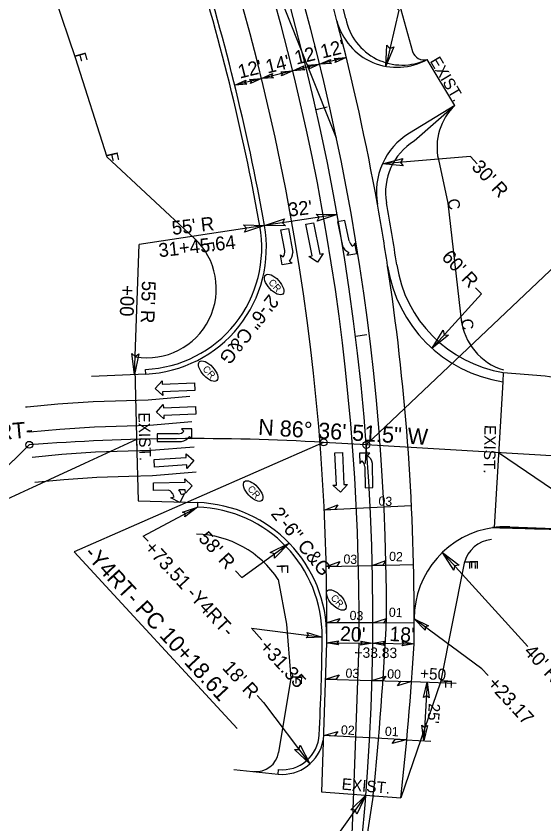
# Model space of a CAD drawing. Extents: x 1702862 to 1704514, y 793768 to 796215.
# Drawn here: x 1703833.9 to 1704063.5, y 794035 to 794386.1 of the extents above; entities that cross this region are included whole.
import ezdxf

# ---------------------------------------------------------------- set-up
doc = ezdxf.new("R2010")
doc.units = 0
for name, color, linetype in [('Exist Horizontal Alignment', 7, 'Continuous'), ('Exist Horizontal Alignment Station Label', 7, 'Continuous'), ('Exist Horizontal Alignment Tick Large', 7, 'Continuous'), ('Old_Level_3', 7, 'Continuous'), ('Prop Conc 2ft 6in Curb and Gutter', 7, 'Continuous'), ('Prop Dimension', 7, 'Continuous'), ('Prop Dimension Text', 7, 'Continuous'), ('Prop DSN Text', 7, 'Continuous'), ('Prop EOT', 7, 'Continuous'), ('Prop Horizontal Alignment', 7, 'Continuous'), ('Prop Horizontal Alignment Direction Label', 7, 'Continuous'), ('Prop Horizontal Alignment Station Label', 7, 'Continuous'), ('Prop Horizontal Alignment Tick Small', 7, 'Continuous'), ('Prop Lane Arrow CELL', 7, 'Continuous'), ('Prop Lane Lines', 7, 'Continuous'), ('Prop Leader Line Medium', 7, 'Continuous'), ('Prop Paved Shoulder', 7, 'Continuous'), ('Prop SS Cut Line', 7, 'Continuous'), ('Prop SS Fill Line', 7, 'Continuous'), ('Prop SS Misc', 7, 'Continuous'), ('Prop SS Transition Line', 7, 'Continuous'), ('Prop Superelevation  Arrow CELL', 7, 'Continuous'), ('Prop Superelevation Label', 7, 'Continuous'), ('Prop Terminator CELL', 7, 'Continuous'), ('Prop WCR CELL', 7, 'Continuous')]:
    doc.layers.add(name, color=color, linetype=linetype)

msp = doc.modelspace()

# ---------------------------------------------------------------- linework, layer by layer
at = {"layer": 'Exist Horizontal Alignment'}
msp.add_line((1703986.29, 794199.72), (1703967.71, 794200.82), dxfattribs=at)
msp.add_arc((1703911.32, 793247.48), 955, 86.61431, 94.30234, dxfattribs=at)
at = {"layer": 'Exist Horizontal Alignment Station Label'}
for p, q in [((1703809.32, 794169.99), (1703839.67, 794199.79)), ((1703967.71, 794200.82), (1703859.14, 794153.32)), ((1703859.14, 794153.32), (1703930.08, 794076.46))]:
    msp.add_line(p, q, dxfattribs=at)
for centre in [(1703967.71, 794200.82), (1703839.67, 794199.79), (1703986.29, 794199.72)]:
    msp.add_circle(centre, 1.5, dxfattribs=at)
at = {"layer": 'Exist Horizontal Alignment Tick Large'}
msp.add_line((1703986.29, 794199.72), (1703985.82, 794191.73), dxfattribs=at)
at = {"layer": 'Old_Level_3'}
for points in [[(1704045.87, 794231.21), (1704074.98, 794228.45), (1704097.71, 794224.72)], [(1704093.48, 794162.67), (1704041.88, 794163.83), (1704068.07, 794163.09)]]:
    msp.add_spline(points, degree=3, dxfattribs=at)
at = {"layer": 'Prop Conc 2ft 6in Curb and Gutter'}
for p, q in [((1703890.33, 794230.53), (1703890.23, 794232.53)), ((1703912.86, 794174.66), (1703912.8, 794172.67)), ((1703947.93, 794056.66), (1703948.13, 794058.65))]:
    msp.add_line(p, q, dxfattribs=at)
for centre, radius, start, end in [((1702989.11, 794124.65), 966, 10.14602, 17.69698), ((1703887.83, 794285.48), 53, 272.5979, 10.146), ((1703911.08, 794116.69), 56, 359.5057, 88.2385), ((1702989.11, 794124.65), 978, 357.01557, 359.50571), ((1703949.8, 794074.56), 16, 264.0066, 357.0156)]:
    msp.add_arc(centre, radius, start, end, dxfattribs=at)
at = {"layer": 'Prop Dimension'}
for p, q in [((1703977.58, 794368.05), (1703960.1, 794363.75)), ((1703960.1, 794363.75), (1703929.03, 794356.1)), ((1703973.64, 794299.88), (1703941.98, 794295.11)), ((1703969.03, 794113.76), (1703989.05, 794113.54)), ((1703989.05, 794113.54), (1704007.05, 794113.34))]:
    msp.add_line(p, q, dxfattribs=at)
msp.add_lwpolyline([(1704033.81, 794268.08), (1704036.35, 794265.34), (1704014.88, 794241.77)], dxfattribs=at)
at = {"layer": 'Prop Dimension Text'}
for p in [(1703941.97, 794295.17), (1703885.5, 794230.32)]:
    msp.add_line(p, (1703887.5, 794286.9), dxfattribs=at)
for points in [[(1703997.7, 794391.74), (1704000.49, 794388.71), (1703994.76, 794364.3)], [(1704034.48, 794321.92), (1704031.62, 794325.02), (1703993.3, 794321.91)], [(1703891.33, 794157.83), (1703889.2, 794160.09), (1703912.79, 794172.69)], [(1703929.42, 794144.98), (1703932.09, 794142.08), (1703952.72, 794157.07)], [(1704056.52, 794112.19), (1704053.8, 794115.14), (1704019.4, 794153.02)], [(1704039.27, 794099.52), (1704036.54, 794102.47), (1704007.11, 794124.19)], [(1703940.9, 794115.03), (1703936.28, 794120.03), (1703967.07, 794116.21)], [(1703938.74, 794090.78), (1703941.53, 794087.76), (1703961.72, 794061.07)]]:
    msp.add_lwpolyline(points, dxfattribs=at)
at = {"layer": 'Prop EOT'}
for p, q in [((1704024.85, 794347.32), (1704012.71, 794367.19)), ((1704024.85, 794347.32), (1704005.02, 794335.21)), ((1703890.33, 794230.53), (1703866.68, 794229.46)), ((1703885.56, 794232.69), (1703886.49, 794197.16)), ((1704045.63, 794227.2), (1704041.88, 794163.83)), ((1703886.36, 794202.16), (1703887.05, 794175.46)), ((1703887.05, 794175.46), (1703912.86, 794174.66)), ((1703969.03, 794113.76), (1703966.73, 794048.94)), ((1703928.6, 794058.69), (1703947.93, 794056.66)), ((1703966.73, 794048.94), (1704001.25, 794046.28))]:
    msp.add_line(p, q, dxfattribs=at)
for centre, radius, start, end in [((1702989.11, 794124.65), 1018, 14.75888, 42.70907), ((1702989.11, 794124.65), 968, 10.14602, 17.69698), ((1703999.63, 794390.86), 27, 194.7589, 299.2661), ((1704020.66, 794309.61), 30, 121.4124, 190.1653), ((1702989.11, 794124.65), 1018, 8.63399, 10.1653), ((1703887.83, 794285.48), 55, 272.5979, 10.146), ((1704054.89, 794286.48), 60, 188.634, 261.1171), ((1703911.08, 794116.69), 58, 359.5057, 88.2385), ((1704047.11, 794124.17), 40, 97.5132, 179.9743), ((1702989.11, 794124.65), 1018, 359.36375, 359.9743), ((1702989.11, 794124.65), 980, 359.36375, 359.50571), ((1702759.73, 794187.37), 1249.51, 353.51674, 356.60361), ((1703949.8, 794074.56), 18, 264.0066, 349.9892)]:
    msp.add_arc(centre, radius, start, end, dxfattribs=at)
at = {"layer": 'Prop Horizontal Alignment'}
msp.add_line((1704163.59, 794189.23), (1703986.29, 794199.72), dxfattribs=at)
msp.add_arc((1702989.11, 794124.65), 1000, 351.25916, 42.70907, dxfattribs=at)
at = {"layer": 'Prop Horizontal Alignment Station Label'}
msp.add_line((1703986.29, 794199.72), (1704135, 794340.88), dxfattribs=at)
for centre in [(1703967.71, 794200.82), (1703839.67, 794199.79), (1703986.29, 794199.72)]:
    msp.add_circle(centre, 1.5, dxfattribs=at)
at = {"layer": 'Prop Horizontal Alignment Tick Small'}
for p, q in [((1703964.41, 794345.53), (1703969.29, 794346.64)), ((1703981.59, 794247.06), (1703986.55, 794247.68)), ((1703988.85, 794147.37), (1703993.85, 794147.48)), ((1703986.13, 794047.45), (1703991.11, 794047.06))]:
    msp.add_line(p, q, dxfattribs=at)
at = {"layer": 'Prop Lane Arrow CELL'}
for p, q in [((1703977, 794297.33), (1703973.77, 794296.66)), ((1703978.86, 794288.37), (1703977, 794297.33)), ((1703949.17, 794293.19), (1703952.42, 794293.77)), ((1703950.79, 794284.18), (1703949.17, 794293.19)), ((1703952.42, 794293.77), (1703954.29, 794283.39)), ((1703960.02, 794295.65), (1703963.26, 794296.3)), ((1703962.8, 794281.93), (1703960.02, 794295.65)), ((1703963.26, 794296.3), (1703966.04, 794282.58)), ((1703973.77, 794296.66), (1703975.92, 794286.33)), ((1703981.31, 794287.4), (1703980.5, 794286.16)), ((1703982.18, 794282.98), (1703981.31, 794287.4)), ((1703967.51, 794282.88), (1703965.09, 794279.18)), ((1703966.04, 794282.58), (1703967.51, 794282.88)), ((1703978.68, 794283.38), (1703977.86, 794282.14)), ((1703977.86, 794282.14), (1703982.18, 794282.98)), ((1703949.73, 794277.94), (1703948.89, 794282.36)), ((1703948.89, 794282.36), (1703950.11, 794281.52)), ((1703952.84, 794279.62), (1703954.05, 794278.77)), ((1703961.33, 794281.63), (1703962.8, 794281.93)), ((1703965.09, 794279.18), (1703961.33, 794281.63)), ((1703954.05, 794278.77), (1703949.73, 794277.94)), ((1703894.47, 794224.24), (1703897.48, 794227.58)), ((1703897.48, 794227.58), (1703897.54, 794226.08)), ((1703897.54, 794226.08), (1703911.53, 794226.69)), ((1703911.53, 794226.69), (1703911.67, 794223.39)), ((1703897.75, 794221.28), (1703894.47, 794224.24)), ((1703911.67, 794223.39), (1703897.68, 794222.78)), ((1703897.68, 794222.78), (1703897.75, 794221.28)), ((1703894.95, 794214.02), (1703897.96, 794217.35)), ((1703897.96, 794217.35), (1703898.02, 794215.86)), ((1703898.02, 794215.86), (1703912.01, 794216.46)), ((1703912.01, 794216.46), (1703912.15, 794213.17)), ((1703898.23, 794211.06), (1703894.95, 794214.02)), ((1703912.15, 794213.17), (1703898.17, 794212.56)), ((1703898.17, 794212.56), (1703898.23, 794211.06)), ((1703910.38, 794206.75), (1703905.88, 794206.78)), ((1703905.88, 794206.78), (1703906.93, 794205.73)), ((1703910.35, 794202.35), (1703910.38, 794206.75)), ((1703904.44, 794204.57), (1703895.29, 794204.52)), ((1703895.29, 794204.52), (1703895.31, 794201.22)), ((1703909.3, 794203.4), (1703910.35, 794202.35)), ((1703895.31, 794201.22), (1703905.86, 794201.28)), ((1703907.94, 794194.3), (1703907.85, 794195.8)), ((1703907.85, 794195.8), (1703911.19, 794192.9)), ((1703972.6, 794196.28), (1703975.89, 794196.44)), ((1703973.27, 794182.3), (1703972.6, 794196.28)), ((1703975.89, 794196.44), (1703976.56, 794182.46)), ((1703987.78, 794196.21), (1703983.38, 794196.19)), ((1703983.38, 794196.19), (1703983.41, 794191.69)), ((1703986.75, 794195.14), (1703987.78, 794196.21)), ((1703893.97, 794193.42), (1703907.94, 794194.3)), ((1703894.18, 794190.13), (1703893.97, 794193.42)), ((1703911.19, 794192.9), (1703908.24, 794189.51)), ((1703983.41, 794191.69), (1703984.44, 794192.76)), ((1703989.09, 794181.18), (1703988.91, 794191.73)), ((1703908.15, 794191.01), (1703894.18, 794190.13)), ((1703908.24, 794189.51), (1703908.15, 794191.01)), ((1703985.63, 794190.27), (1703985.79, 794181.13)), ((1703907.44, 794183.56), (1703907.4, 794185.06)), ((1703907.4, 794185.06), (1703910.58, 794181.99)), ((1703893.64, 794183.22), (1703907.44, 794183.56)), ((1703893.72, 794179.92), (1703893.64, 794183.22)), ((1703910.58, 794181.99), (1703907.56, 794178.76)), ((1703971.77, 794182.23), (1703973.27, 794182.3)), ((1703975.12, 794179.23), (1703971.77, 794182.23)), ((1703978.06, 794182.53), (1703975.12, 794179.23)), ((1703976.56, 794182.46), (1703978.06, 794182.53)), ((1703985.79, 794181.13), (1703989.09, 794181.18)), ((1703900.17, 794180.08), (1703893.72, 794179.92)), ((1703907.52, 794180.26), (1703904.67, 794180.19)), ((1703907.26, 794178.55), (1703905.16, 794174.65)), ((1703905.82, 794178.12), (1703907.26, 794178.55)), ((1703907.56, 794178.76), (1703907.52, 794180.26)), ((1703901.25, 794176.75), (1703902.64, 794177.19)), ((1703905.16, 794174.65), (1703901.25, 794176.75))]:
    msp.add_line(p, q, dxfattribs=at)
for centre, radius, start, end in [((1703980.82, 794288.16), 5.25, 200.4214, 245.7331), ((1703982.06, 794289.03), 3.28, 191.7453, 241.4035), ((1703947.59, 794283.59), 3.28, 320.5495, 10.2077), ((1703949.06, 794283.25), 5.25, 316.22, 1.5316), ((1703904.43, 794207.83), 3.28, 270.3139, 319.9721), ((1703905.04, 794206.45), 5.25, 278.99, 324.3017), ((1703983.75, 794190.85), 5.25, 9.6424, 54.9541), ((1703982.37, 794190.23), 3.28, 0.9663, 50.6245), ((1703899.59, 794177.62), 2.52, 40.4837, 76.7957), ((1703898.32, 794176.18), 4.43, 13.1202, 43.9738), ((1703901.49, 794177.12), 4.43, 13.0014, 43.88)]:
    msp.add_arc(centre, radius, start, end, dxfattribs=at)
at = {"layer": 'Prop Lane Lines'}
for p, q in [((1703973.28, 794333.07), (1703936.62, 794425.07)), ((1704048.71, 794164.14), (1704103.67, 794161.95)), ((1703983.02, 794113.28), (1703980.78, 794048.9)), ((1703980.78, 794048.9), (1703977.5, 793972.68)), ((1703989.31, 794047.5), (1703977.5, 793972.68))]:
    msp.add_line(p, q, dxfattribs=at)
for points in [[(1703838.03, 794216.26), (1703838.72, 794216.34), (1703852.02, 794217.6), (1703867.42, 794218.64), (1703881.99, 794219.09), (1703891.41, 794219.37), (1703909.53, 794220.88)], [(1703839.86, 794205.39), (1703852.92, 794206.63), (1703867.97, 794207.65), (1703882.32, 794208.1), (1703892.03, 794208.38), (1703910.44, 794209.92)], [(1703840.99, 794194.45), (1703853.81, 794195.67), (1703868.51, 794196.66), (1703882.65, 794197.1), (1703892.65, 794197.4), (1703911.36, 794198.95)], [(1703842.12, 794183.51), (1703854.7, 794184.7), (1703869.05, 794185.67), (1703882.99, 794186.11), (1703893.27, 794186.41), (1703912.27, 794187.99)]]:
    msp.add_lwpolyline(points, dxfattribs=at)
for centre, radius, start, end in [((1702989.11, 794124.65), 1006, 0.00687, 42.70907), ((1702989.11, 794124.65), 994, 359.40932, 42.70907), ((1702989.11, 794124.65), 980, 359.40932, 42.70907), ((1702989.11, 794124.65), 1018, 10.1653, 14.75888), ((1702989.11, 794124.65), 1018, 359.9743, 8.63399), ((1704047.11, 794124.17), 40, 87.7131, 97.5132), ((1702558.47, 794193.95), 1438.32, 354.15599, 357.24285)]:
    msp.add_arc(centre, radius, start, end, dxfattribs=at)
at = {"layer": 'Prop Leader Line Medium'}
for p, q in [((1703886.36, 794202.16), (1703779.4, 794152.94)), ((1704149.5, 794124.08), (1704043.8, 794196.32)), ((1703986.13, 794047.45), (1703866.27, 793881.64))]:
    msp.add_line(p, q, dxfattribs=at)
at = {"layer": 'Prop Paved Shoulder'}
for p, q in [((1704024.85, 794347.32), (1704007.11, 794331.8)), ((1704045.87, 794231.21), (1704045.63, 794227.2))]:
    msp.add_line(p, q, dxfattribs=at)
for centre, radius, start, end in [((1702989.11, 794124.65), 1022, 14.75888, 18.93305), ((1704001.96, 794389.87), 25.05, 191.2148, 295.722), ((1704020.66, 794309.61), 26, 121.4124, 190.1653), ((1702989.11, 794124.65), 1022, 8.63399, 10.1653), ((1704054.89, 794286.48), 56, 188.634, 260.7231)]:
    msp.add_arc(centre, radius, start, end, dxfattribs=at)
at = {"layer": 'Prop SS Cut Line'}
for p, q in [((1703996.51, 794406.41), (1704006.42, 794370.71)), ((1704017.63, 794323.78), (1704021.82, 794304.82)), ((1704021.82, 794304.82), (1704027.73, 794252.76))]:
    msp.add_line(p, q, dxfattribs=at)
for centre, radius, start, end in [((1704011.24, 794372.05), 5, 195.5278, 288.5337), ((1704042.04, 794329.17), 25, 133.4523, 192.4595), ((1704053.39, 794257.27), 26, 186.4769, 253.3442)]:
    msp.add_arc(centre, radius, start, end, dxfattribs=at)
at = {"layer": 'Prop SS Fill Line'}
for p, q in [((1703839.4, 794427.8), (1703859.6, 794368.12)), ((1703859.6, 794368.12), (1703873.4, 794324.92)), ((1703873.4, 794324.92), (1703911.44, 794289.63)), ((1704028.92, 794148.28), (1704018.54, 794096.56)), ((1703953.39, 794098.34), (1703948.14, 794066.12))]:
    msp.add_line(p, q, dxfattribs=at)
msp.add_lwpolyline([(1703947.98, 794141.22), (1703951.56, 794121.84), (1703953.39, 794098.34)], dxfattribs=at)
for centre, radius, start, end in [((1703891.03, 794267.64), 30, 260.1886, 47.1443), ((1703911.08, 794116.69), 44.32, 33.6097, 88.2385)]:
    msp.add_arc(centre, radius, start, end, dxfattribs=at)
at = {"layer": 'Prop SS Transition Line'}
msp.add_line((1704018.54, 794096.56), (1704001.25, 794046.28), dxfattribs=at)
for centre, radius, start, end in [((1704041.81, 794145.42), 13.2, 94.5539, 167.5024), ((1703938.27, 794067.73), 10, 264.0066, 350.7431)]:
    msp.add_arc(centre, radius, start, end, dxfattribs=at)
at = {"layer": 'Prop Superelevation  Arrow CELL'}
for p, q in [((1703968.48, 794097.93), (1703988.74, 794097.38)), ((1703988.74, 794097.38), (1704005.96, 794096.91)), ((1703987.74, 794072.4), (1703967.77, 794073.44)), ((1704003.62, 794071.57), (1703987.74, 794072.4)), ((1703966.73, 794048.94), (1704001.25, 794046.28))]:
    msp.add_line(p, q, dxfattribs=at)
for points in [[(1703967.99, 794171.4), (1703973.89, 794173.68), (1703972.61, 794171.62)], [(1703988.85, 794147.37), (1703994.8, 794149.5), (1703993.48, 794147.47)], [(1703968.86, 794146.92), (1703974.81, 794149.06), (1703973.48, 794147.02)], [(1703968.79, 794122.42), (1703974.81, 794124.35), (1703973.42, 794122.37)], [(1703989.11, 794122.37), (1703995.13, 794124.29), (1703993.73, 794122.31)], [(1703968.48, 794097.93), (1703974.53, 794099.76), (1703973.1, 794097.8)], [(1703988.74, 794097.38), (1703994.79, 794099.2), (1703993.36, 794097.24)], [(1704005.96, 794096.91), (1703999.92, 794095.05), (1704001.34, 794097.02)], [(1703967.77, 794073.44), (1703973.86, 794075.14), (1703972.39, 794073.21)], [(1704003.62, 794071.57), (1703997.51, 794069.93), (1703999, 794071.84)]]:
    msp.add_lwpolyline(points, close=True, dxfattribs=at)
at = {"layer": 'Prop Superelevation Label'}
for p, q in [((1703987.97, 794172.35), (1703967.99, 794171.4)), ((1704005.95, 794173.21), (1703987.97, 794172.35)), ((1703968.86, 794146.92), (1703988.85, 794147.37)), ((1703988.85, 794147.37), (1704006.85, 794147.78)), ((1703989.11, 794122.37), (1703968.79, 794122.42)), ((1704007.02, 794122.33), (1703989.11, 794122.37)), ((1704005.96, 794096.86), (1704025.4, 794096.22)), ((1704012.76, 794096.63), (1704011.3, 794071.12)), ((1704003.62, 794071.57), (1704014.29, 794070.94))]:
    msp.add_line(p, q, dxfattribs=at)
for points in [[(1704011.22, 794089.96), (1704012.76, 794096.63), (1704013.57, 794089.79), (1704012.42, 794090.72)], [(1704012.85, 794077.79), (1704011.3, 794071.12), (1704010.49, 794077.96), (1704011.64, 794077.03)]]:
    msp.add_lwpolyline(points, close=True, dxfattribs=at)
at = {"layer": 'Prop Terminator CELL'}
for points in [[(1703998.33, 794372.71), (1703994.76, 794364.3), (1703995.27, 794373.48), (1703996.57, 794372)], [(1703971.17, 794365.56), (1703965.93, 794365.18), (1703970.76, 794367.32), (1703970.34, 794366.27)], [(1703972.34, 794367.68), (1703977.58, 794368.05), (1703972.75, 794365.92), (1703973.17, 794366.97)], [(1703959.52, 794362.69), (1703954.28, 794362.32), (1703959.11, 794364.45), (1703958.69, 794363.4)], [(1703960.69, 794364.81), (1703965.93, 794365.18), (1703961.1, 794363.05), (1703961.52, 794364.1)], [(1703945.92, 794359.34), (1703940.68, 794358.97), (1703945.52, 794361.11), (1703945.09, 794360.05)], [(1703949.04, 794361.94), (1703954.28, 794362.32), (1703949.44, 794360.18), (1703949.87, 794361.23)], [(1703934.27, 794356.47), (1703929.03, 794356.1), (1703933.86, 794358.24), (1703933.44, 794357.18)], [(1703935.45, 794358.6), (1703940.68, 794358.97), (1703935.85, 794356.83), (1703936.27, 794357.88)], [(1704002.39, 794321.09), (1703993.3, 794321.91), (1704002.19, 794324.24), (1704001.17, 794322.55)], [(1703951.11, 794294.92), (1703941.98, 794295.11), (1703950.69, 794298.04), (1703949.79, 794296.29)], [(1703964.51, 794300.08), (1703973.64, 794299.88), (1703964.93, 794296.95), (1703965.82, 794298.71)], [(1703932.84, 794295.36), (1703941.97, 794295.17), (1703933.26, 794292.24), (1703934.16, 794293.99)], [(1704022.09, 794247.38), (1704014.88, 794241.77), (1704019.79, 794249.54), (1704020.2, 794247.61)], [(1703887.36, 794239.26), (1703885.5, 794230.32), (1703884.22, 794239.42), (1703885.78, 794238.21)], [(1703906.29, 794170.51), (1703912.8, 794172.67), (1703907.37, 794168.41), (1703907.57, 794169.87)], [(1703944.52, 794153.03), (1703952.72, 794157.07), (1703946.33, 794150.45), (1703946.32, 794152.42)], [(1704024.3, 794145.32), (1704019.4, 794153.02), (1704026.67, 794147.4), (1704024.71, 794147.17)], [(1704011.85, 794119.25), (1704007.11, 794124.19), (1704013.28, 794121.13), (1704011.88, 794120.67)], [(1703960.52, 794118.19), (1703967.07, 794116.21), (1703960.19, 794115.85), (1703961.19, 794116.94)], [(1703974.19, 794112.82), (1703969.03, 794113.76), (1703974.24, 794114.63), (1703973.57, 794113.71)], [(1703983.88, 794114.49), (1703989.05, 794113.54), (1703983.83, 794112.68), (1703984.51, 794113.59)], [(1703994.23, 794112.59), (1703989.07, 794113.54), (1703994.28, 794114.4), (1703993.61, 794113.49)], [(1704001.88, 794114.29), (1704007.05, 794113.34), (1704001.83, 794112.48), (1704002.5, 794113.39)], [(1703957.53, 794069.18), (1703961.72, 794061.07), (1703954.98, 794067.32), (1703956.95, 794067.37)], [(1703979.6, 794041.06), (1703986.13, 794047.45), (1703982.12, 794039.18), (1703981.5, 794041.05)]]:
    msp.add_lwpolyline(points, close=True, dxfattribs=at)
at = {"layer": 'Prop WCR CELL'}
for centre in [(1703946.19, 794269.44), (1703917.51, 794231.8), (1703937.07, 794179.68), (1703973.26, 794132.33)]:
    msp.add_ellipse(centre, major_axis=(3.8, -4.12), ratio=0.462467, dxfattribs=at)

# ---------------------------------------------------------------- texts
at = {"layer": 'Exist Horizontal Alignment Station Label'}
msp.add_text('-Y4RT- PC 10+18.61', height=7, rotation=312.7091, dxfattribs=at).set_placement((1703863.14, 794152.23))
at = {"layer": 'Prop Dimension'}
for s, height, rotation, p in [("32'", 6, 6.4236, (1703952.65, 794298.96)), ("20'", 6.3, 356.8874, (1703974.74, 794114.65)), ("18'", 6.3, 356.8874, (1703996.22, 794114.54))]:
    msp.add_text(s, height=height, rotation=rotation, dxfattribs=at).set_placement(p)
at = {"layer": 'Prop Dimension Text'}
for s, rotation, p in [("12'", 13.8336, (1703967.17, 794367.64)), ("12'", 13.8336, (1703955.88, 794364.97)), ("12'", 13.8336, (1703931.24, 794358.9)), ("14'", 13.8336, (1703943.32, 794361.11)), ("30' R", 312.7091, (1704031.72, 794320.26)), ("55' R", 6.4236, (1703902, 794291)), ('31+45.64', 6.4236, (1703896.22, 794281.28)), ("60' R", 312.7091, (1704018.69, 794281.06)), ('+00', 267.9768, (1703879.51, 794269.28)), ("55' R", 267.9768, (1703888.72, 794271.14)), ('2\'-6" C&G', 231.5769, (1703944.07, 794265.61)), ("58' R", 312.7091, (1703912.9, 794158.81)), ('+73.51 -Y4RT-', 312.7091, (1703889.39, 794154.69)), ('+31.35', 312.7091, (1703939.41, 794111.71)), ("40' R", 312.7091, (1704054.49, 794109.65)), ("18' R", 312.7091, (1703923.3, 794102.61)), ('+23.17', 312.7091, (1704038.54, 794095.69))]:
    msp.add_text(s, height=6, rotation=rotation, dxfattribs=at).set_placement(p)
at = {"layer": 'Prop DSN Text'}
for s, height, rotation, p in [('EXIST.', 5, 300.6784, (1704013.78, 794366.61)), ('EXIST.', 5, 271.4976, (1703887.11, 794213.81)), ('EXIST.', 5, 268.8881, (1704037.73, 794208.46)), ('2\'-6" C&G', 6, 309.2167, (1703944.48, 794169.7)), ('EXIST.', 5, 354.8849, (1703975.39, 794049.95))]:
    msp.add_text(s, height=height, rotation=rotation, dxfattribs=at).set_placement(p)
at = {"layer": 'Prop Horizontal Alignment Direction Label'}
for s, rotation, p in [('-Y4RT-', 5.163, (1703811.43, 794200.4)), ('N 86%%d 36\' 51.5" W', 356.6143, (1703939.12, 794204.07))]:
    msp.add_text(s, height=7, rotation=rotation, dxfattribs=at).set_placement(p)
at = {"layer": 'Prop SS Misc'}
for s, rotation, p in [('F', 285.626, (1703859.22, 794369.48)), ('F', 282.7612, (1703873.09, 794326.31)), ('C', 279.8964, (1704021.56, 794306.33)), ('F', 279.8964, (1703914.89, 794287.6)), ('C', 277.0316, (1704027.54, 794254.28)), ('F', 271.3021, (1704028.88, 794149.7)), ('F', 271.3021, (1704029.8, 794149.72)), ('F', 271.3021, (1703947.3, 794147.84)), ('F', 268.4373, (1703953.43, 794099.76)), ('F', 268.4373, (1704018.57, 794097.98)), ('F', 268.4373, (1704018.57, 794097.98))]:
    msp.add_text(s, height=5, rotation=rotation, dxfattribs=at).set_placement(p)
at = {"layer": 'Prop Superelevation Label'}
for s, height, rotation, p in [('03', 4, 357.7211, (1703991.52, 794173.38)), ('02', 4, 357.7211, (1703996.15, 794149.35)), ('03', 4, 357.7211, (1703976.28, 794148.19)), ('01', 4, 357.7211, (1703996.04, 794125.07)), ('03', 4, 357.7211, (1703978.95, 794123.67)), ('+33.83', 4.5, 359.4566, (1703981.12, 794107.26)), ('03', 4, 357.7211, (1703977.17, 794098.6)), ('00', 4, 357.7211, (1703995.32, 794098.28)), ('+50', 5, 356.6708, (1704009.55, 794098.04)), ("25'", 5, 266.158, (1704013.49, 794087.52)), ('02', 4, 357.7211, (1703975.19, 794073.91)), ('01', 4, 357.7211, (1703994.32, 794073.32))]:
    msp.add_text(s, height=height, rotation=rotation, dxfattribs=at).set_placement(p)
at = {"layer": 'Prop WCR CELL'}
for p in [(1703943.5, 794270.17), (1703914.83, 794232.53), (1703934.39, 794180.41), (1703970.57, 794133.06)]:
    msp.add_text('CR', height=3, rotation=312.7091, dxfattribs=at).set_placement(p)

doc.saveas('drawing.dxf')
